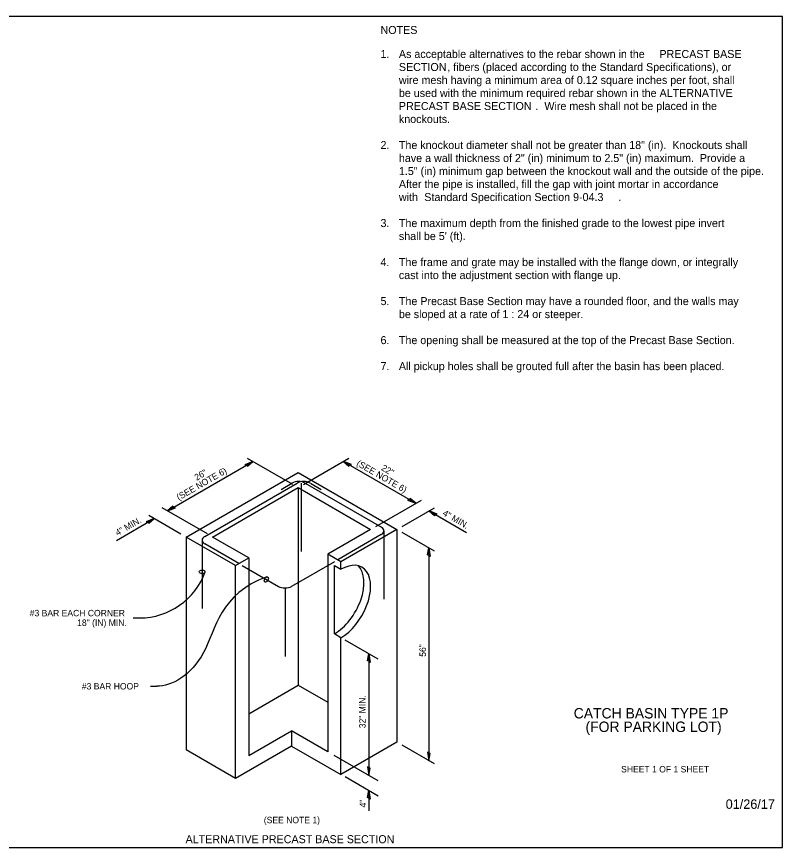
# Model space of a CAD drawing. Extents: x 99862 to 103151, y 100000 to 102076.
# Drawn here: x 101238 to 103151, y 100000 to 102076 of the extents above; entities that cross this region are included whole.
import ezdxf

# ---------------------------------------------------------------- set-up
doc = ezdxf.new("R2010")
doc.units = 0
for name, color, linetype in [('Level 1', 7, 'Continuous'), ('Level 10', 7, 'Continuous'), ('Level 11', 7, 'Continuous'), ('Level 15', 7, 'Continuous'), ('Level 17', 7, 'Continuous'), ('Level 20', 7, 'Continuous'), ('Level 44', 7, 'Continuous'), ('Level 60', 7, 'Continuous'), ('Level 62', 7, 'Continuous'), ('Level 8', 7, 'Continuous')]:
    doc.layers.add(name, color=color, linetype=linetype)

msp = doc.modelspace()

# ---------------------------------------------------------------- linework, layer by layer
at = {"layer": 'Level 1'}
msp.add_lwpolyline([(99862, 99999.5), (103151, 99999.5), (103151, 102075.5), (99862, 102075.5)], close=True, dxfattribs=at)
at = {"layer": 'Level 10'}
for p, q in [((101948.9, 100909.9), (101948.9, 100738.9)), ((101958.9, 100909.7), (101958.9, 100909.7)), ((102149.6, 100799.6), (102149, 100800)), ((102155.8, 100790.5), (102155.8, 100619.5)), ((101708.5, 100776.7), (101708.5, 100776.7)), ((102149, 100781), (102040.2, 100718.2)), ((101701.7, 100767.2), (101701.7, 100596.2)), ((101708.5, 100757.7), (101708.5, 100757.7))]:
    msp.add_line(p, q, dxfattribs=at)
for points in [[(101708.5, 100776.7), (101939, 100909.7)], [(101898.9, 100894.1), (101926, 100909.7)], [(101958.9, 100909.7), (102149.6, 100799.6)], [(101971.9, 100909.7), (101998.9, 100894.1)], [(101793.4, 100708.7), (101708.5, 100757.7)]]:
    msp.add_lwpolyline(points, dxfattribs=at)
for centre, major_axis, start_param, end_param in [((101942.4, 100900.2), (-23.3, 0), 3.926991, 5.497787), ((101955.4, 100900.2), (-23.3, 0), 3.926991, 5.497787), ((102132.5, 100790.5), (23.3, 0), 5.497787, 7.068583), ((101724.9, 100767.2), (-23.3, 0), 5.497787, 7.068583)]:
    msp.add_ellipse(centre, major_axis=major_axis, ratio=0.57735, start_param=start_param, end_param=end_param, dxfattribs=at)
at = {"layer": 'Level 11'}
for p, q in [((101661.8, 100775.1), (101941.5, 100936.6)), ((101941.5, 100936.6), (102188.2, 100794.1)), ((101727.6, 100775.1), (101941.5, 100898.6)), ((101941.5, 100898.6), (101941.5, 100404.7)), ((101941.5, 100898.6), (102122.4, 100794.1)), ((102122.4, 100794.1), (102015.5, 100732.4)), ((102188.2, 100794.1), (102048.4, 100713.4)), ((102188.2, 100794.1), (102188.2, 100262.2)), ((101661.8, 100775.1), (101661.8, 100243.2)), ((101785.2, 100703.9), (101661.8, 100775.1)), ((101818.1, 100722.9), (101727.6, 100775.1)), ((102100.7, 100699.6), (102100.7, 100699.6)), ((101818.1, 100333.5), (101941.5, 100404.7)), ((101941.5, 100404.7), (102015.5, 100362)), ((102188.2, 100262.2), (102048.4, 100181.5)), ((101785.2, 100172), (101661.8, 100243.2))]:
    msp.add_line(p, q, dxfattribs=at)
for points in [[(102117.6, 100483.4), (102121, 100461.8), (102117.6, 100464.7), (102114.3, 100465.7)], [(102117.6, 100179.5), (102121, 100197.2), (102117.6, 100198.2), (102114.3, 100201.1)], [(102117.6, 100141.5), (102121, 100119.9), (102117.6, 100122.8), (102114.3, 100123.8)]]:
    msp.add_lwpolyline(points, close=True, dxfattribs=at)
for centre, major_axis, start_param, end_param in [((102048.4, 100608.9), (-52.3, -90.7), 0.785398, 3.926991), ((102031.9, 100618.4), (52.3, 90.7), 3.926991, 6.125397)]:
    msp.add_ellipse(centre, major_axis=major_axis, ratio=0.57735, start_param=start_param, end_param=end_param, dxfattribs=at)
at = {"layer": 'Level 15'}
for p, q in [((101614.8, 100840.4), (101828.3, 100963.8)), ((101928.5, 100906.1), (101814.6, 100971.6)), ((101954.6, 100906.1), (102068.1, 100971.9)), ((102054.4, 100963.9), (102235.3, 100859.3)), ((102135.5, 100801.6), (102249.2, 100867.3)), ((101714.6, 100782.7), (101601.7, 100847.8)), ((102201.2, 100801.6), (102282, 100848.1)), ((102268.3, 100840.2), (102361.9, 100786.1)), ((101487.4, 100766.6), (101581.9, 100821.3)), ((101648.6, 100782.6), (101568.2, 100829.2)), ((102282.1, 100739.9), (102201.2, 100786.6)), ((102268.2, 100747.9), (102268.2, 100216)), ((101529.3, 100573), (101545.3, 100573)), ((102141.7, 100469.6), (102058.8, 100517.5)), ((102117.6, 100483.4), (102117.6, 100179.5)), ((101572.5, 100402.1), (101588.5, 100402.1)), ((102281.8, 100208.2), (102201.2, 100254.7)), ((102141.7, 100165.6), (102031.3, 100229.4)), ((102141.7, 100127.6), (102058.8, 100175.5)), ((102117.6, 100141.5), (102117.6, 100090.9))]:
    msp.add_line(p, q, dxfattribs=at)
msp.add_arc((101545.3, 100747.3), 174.3, 270, 340.1414, dxfattribs=at)
for centre, major_axis in [((101701.7, 100688.1), (-7.5, 0)), ((101862, 100669), (3.75, 6.5))]:
    msp.add_ellipse(centre, major_axis=major_axis, ratio=0.57735, dxfattribs=at)
msp.add_open_spline([(101863, 100675.6), (101746.8, 100633.7), (101724.5, 100455), (101624.3, 100402.1), (101588.5, 100402.1)], degree=3, dxfattribs=at)
at = {"layer": 'Level 17'}
for p, q in [((102031.9, 100713.4), (101925, 100651.7)), ((101801.6, 100703.9), (101892.1, 100651.7)), ((101908.6, 100647.7), (101908.6, 100476.8))]:
    msp.add_line(p, q, dxfattribs=at)
msp.add_ellipse((101908.6, 100661.2), major_axis=(23.3, 0), ratio=0.57735, start_param=3.926987, end_param=5.497787, dxfattribs=at)
at = {"layer": 'Level 44'}
for points in [[(102015.5, 100238.5), (101925, 100290.7), (101925, 100252.7), (102048.4, 100181.5), (102048.4, 100523.4), (102031.9, 100532.9), (102031.9, 100703.9), (102048.4, 100694.4), (102048.4, 100713.4), (102015.5, 100732.4)], [(101818.1, 100229), (101925, 100290.7), (101925, 100252.7), (101785.2, 100172), (101785.2, 100703.9), (101818.1, 100722.9)]]:
    msp.add_lwpolyline(points, close=True, dxfattribs=at)
at = {"layer": 'Level 60'}
msp.add_line((103151, 102075.5), (103151, 102075.5), dxfattribs=at)
at = {"layer": 'Level 8'}
for points in [[(101828.3, 100963.8), (101808, 100955.8), (101812.1, 100954.4), (101814.6, 100952)], [(102054.4, 100963.9), (102068.1, 100952.2), (102070.6, 100954.6), (102074.8, 100956)], [(101614.8, 100840.4), (101635.2, 100848.3), (101631.1, 100849.7), (101628.5, 100852.1)], [(102235.3, 100859.3), (102221.6, 100871), (102219.1, 100868.6), (102215, 100867.2)], [(102268.3, 100840.2), (102281.9, 100828.5), (102284.5, 100830.8), (102288.6, 100832.3)], [(101581.9, 100821.3), (101561.5, 100813.4), (101565.7, 100811.9), (101568.2, 100809.5)], [(102268.2, 100747.9), (102271.6, 100726.4), (102268.2, 100729.2), (102264.9, 100730.2)], [(102268.2, 100216), (102271.6, 100233.8), (102268.2, 100234.8), (102264.9, 100237.6)]]:
    msp.add_lwpolyline(points, close=True, dxfattribs=at)

# ---------------------------------------------------------------- texts
at = {"layer": 'Level 15'}
msp.add_text('01/26/17', height=23.62, dxfattribs=at).set_placement((103009.4, 100095.8))
at = {"layer": 'Level 20'}
for s, height, p in [('NOTES', 20, (102147.2, 102032.1)), ('1.', 20, (102147.2, 101972.1)), ('As acceptable alternatives to the rebar shown in the ', 20, (102193.1, 101972.1)), ('PRECAST BASE', 20, (102843.9, 101972.1)), ('SECTION', 20, (102193.1, 101939.6)), (', fibers (placed according to the Standard Specifications), or', 20, (102313.9, 101939.6)), ('wire mesh having a minimum area of 0.12 square inches per foot, shall', 20, (102193.1, 101907.1)), ('be used with the minimum required rebar shown in the ALTERNATIVE', 20, (102193.1, 101874.6)), ('PRECAST BASE SECTION', 20, (102193.1, 101842.1)), ('.  Wire mesh shall not be placed in the', 20, (102534.2, 101842.1)), ('knockouts.', 20, (102193.1, 101809.6)), ('The knockout diameter shall not be greater than 18" (in).  Knockouts shall', 20, (102193.1, 101744.6)), ('2.', 20, (102147.2, 101744.6)), ('have a wall thickness of 2" (in) minimum to 2.5" (in) maximum.  Provide a', 20, (102193.1, 101712.1)), ('1.5" (in) minimum gap between the knockout wall and the outside of the pipe.', 20, (102193.1, 101679.6)), ('After the pipe is installed, fill the gap with joint mortar in accordance', 20, (102193.1, 101647.1)), ('with ', 20, (102193.1, 101614.6)), ('Standard Specification Section 9-04.3', 20, (102256.5, 101614.6)), ('.', 20, (102741.1, 101614.6)), ('3.', 20, (102147.2, 101549.6)), ('The maximum depth from the finished grade to the lowest pipe invert', 20, (102193.1, 101549.6)), ("shall be 5' (ft).", 20, (102193.1, 101517.1)), ('4.', 20, (102147.2, 101452.1)), ('The frame and grate may be installed with the flange down, or integrally', 20, (102193.1, 101452.1)), ('cast into the adjustment section with flange up.  ', 20, (102193.1, 101419.6)), ('5.', 20, (102147.2, 101354.6)), ('The Precast Base Section may have a rounded floor, and the walls may', 20, (102193.1, 101354.6)), ('be sloped at a rate of 1 : 24 or steeper.', 20, (102193.1, 101322.1)), ('6.', 20, (102147.2, 101257.1)), ('The opening shall be measured at the top of the Precast Base Section.', 20, (102193.1, 101257.1)), ('7.', 20, (102147.2, 101192.1)), ('All pickup holes shall be grouted full after the basin has been placed.', 20, (102193.1, 101192.1)), ('#3 BAR EACH CORNER', 16, (101271, 100577)), ('18" (IN) MIN.', 16, (101389.4, 100553)), ('#3 BAR HOOP', 16, (101401.1, 100394.1)), ('(SEE NOTE 1)', 16, (101855.7, 100059.9)), ('ALTERNATIVE PRECAST BASE SECTION', 20, (101660.2, 100010))]:
    msp.add_text(s, height=height, dxfattribs=at).set_placement(p)
for s, rotation, p in [('(SEE NOTE 6)', 330.0271, (102085.6, 100954.8)), ('(SEE NOTE 6)', 29.9987, (101643.5, 100865.8)), ('26"', 29.9987, (101688, 100915.5)), ('  22"', 330.0271, (102137.1, 100949.2)), ('4" MIN.', 330.0271, (102300.7, 100830.2)), ('4" MIN.', 29.9987, (101490.5, 100777.3)), ('56"', 90.0001, (102260.5, 100475.8)), ('32" MIN.', 90.0001, (102109.8, 100297.3)), ('4"', 90.0001, (102111, 100099.3))]:
    msp.add_text(s, height=16, rotation=rotation, dxfattribs=at).set_placement(p)
at = {"layer": 'Level 62'}
for s, height, p in [('CATCH BASIN TYPE 1P', 26, (102629.8, 100321.7)), ('(FOR PARKING LOT)', 26, (102659.3, 100287.9)), ('SHEET 1 OF 1 SHEET', 16, (102748.2, 100186.8))]:
    msp.add_text(s, height=height, dxfattribs=at).set_placement(p)

doc.saveas('drawing.dxf')
